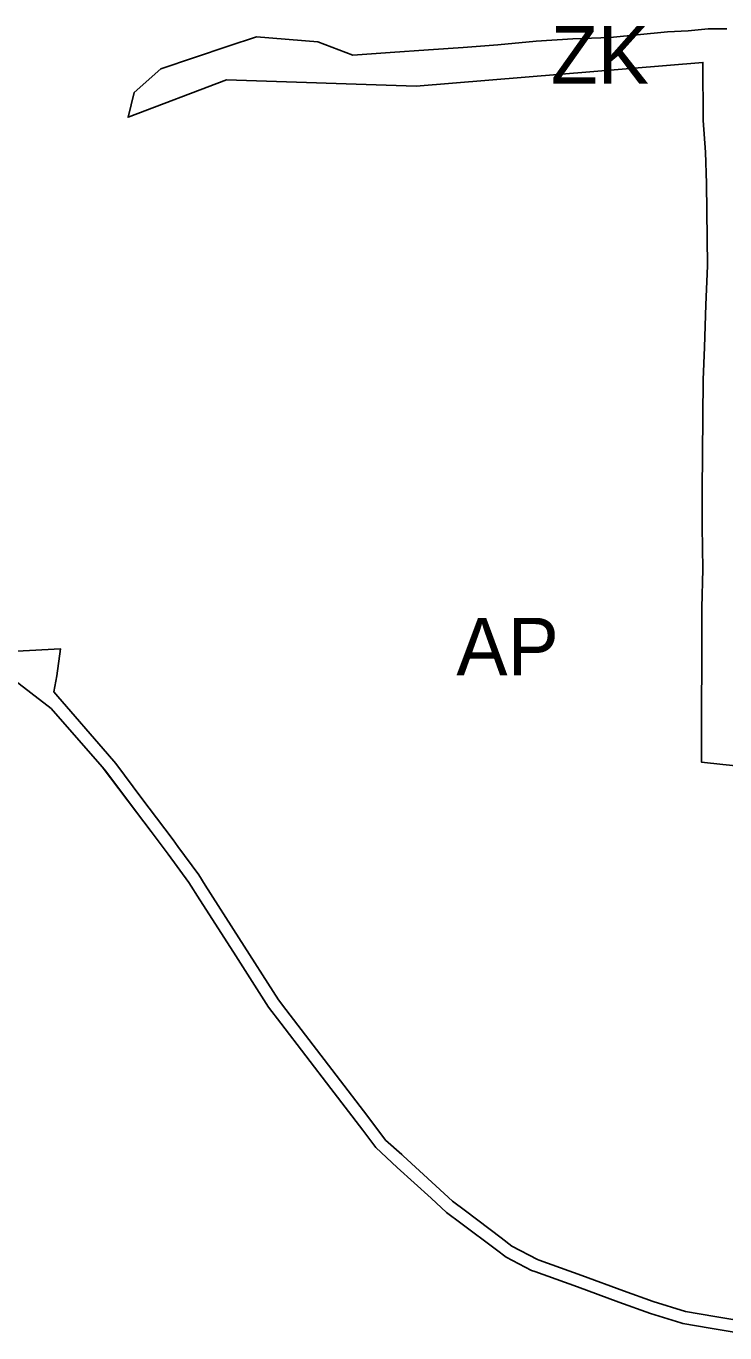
# Model space of a CAD drawing. Extents: x -555509 to -553005, y -1186756 to -1182560.
# Drawn here: x -553469.7 to -553299.5, y -1185459.8 to -1185141.6 of the extents above; entities that cross this region are included whole.
import ezdxf

# ---------------------------------------------------------------- set-up
doc = ezdxf.new("R2010")
doc.units = 0
for name, color, linetype in [('Level 26', 7, 'Continuous'), ('Level 59', 7, 'Continuous'), ('OBRYS_PLOCH', 7, 'Continuous'), ('stav_AP', 7, 'Continuous'), ('stav_ZK', 7, 'Continuous')]:
    doc.layers.add(name, color=color, linetype=linetype)

msp = doc.modelspace()

# ---------------------------------------------------------------- linework, layer by layer
at = {"layer": 'Level 26'}
for p, q in [((-553461.36, -1185293.2), (-553476.51, -1185294.08)), ((-553462.26, -1185299.83), (-553461.36, -1185293.2)), ((-553462.95, -1185303.71), (-553462.26, -1185299.83)), ((-553462, -1185304.81), (-553462.95, -1185303.71)), ((-553449.94, -1185318.8), (-553462, -1185304.81)), ((-553447.88, -1185321.19), (-553449.94, -1185318.8)), ((-553441.55, -1185329.66), (-553447.88, -1185321.19)), ((-553451.19, -1185321.97), (-553450.28, -1185323)), ((-553450.28, -1185323), (-553442.81, -1185332.99)), ((-553438.01, -1185334.39), (-553441.55, -1185329.66)), ((-553433.89, -1185339.72), (-553438.01, -1185334.39)), ((-553432.77, -1185341.4), (-553433.89, -1185339.72)), ((-553427.7, -1185348.29), (-553432.77, -1185341.4)), ((-553426.09, -1185350.82), (-553427.7, -1185348.29)), ((-553417.9, -1185363.63), (-553426.09, -1185350.82)), ((-553408.27, -1185378.71), (-553417.9, -1185363.63)), ((-553406.48, -1185381.05), (-553408.27, -1185378.71)), ((-553410.67, -1185380.52), (-553407.73, -1185384.36)), ((-553394.24, -1185397.05), (-553406.48, -1185381.05)), ((-553386.51, -1185407.16), (-553394.24, -1185397.05)), ((-553382.16, -1185412.85), (-553386.51, -1185407.16)), ((-553378.22, -1185416.39), (-553382.16, -1185412.85)), ((-553384.55, -1185414.66), (-553379.38, -1185419.52)), ((-553377.9, -1185416.68), (-553378.22, -1185416.39)), ((-553369.95, -1185423.98), (-553377.9, -1185416.68)), ((-553379.38, -1185419.52), (-553371.11, -1185427.02)), ((-553365.88, -1185427.72), (-553369.95, -1185423.98)), ((-553371.11, -1185427.02), (-553367.32, -1185430.47)), ((-553362.73, -1185430.11), (-553365.88, -1185427.72)), ((-553367.32, -1185430.47), (-553363.86, -1185433.06)), ((-553354.06, -1185436.68), (-553362.73, -1185430.11)), ((-553351.41, -1185438.69), (-553354.06, -1185436.68)), ((-553345.21, -1185441.93), (-553351.41, -1185438.69)), ((-553352.8, -1185441.34), (-553346.6, -1185444.59)), ((-553344.81, -1185442.08), (-553345.21, -1185441.93)), ((-553334.41, -1185445.85), (-553344.81, -1185442.08)), ((-553346.6, -1185444.59), (-553345.86, -1185444.86)), ((-553345.86, -1185444.86), (-553335.47, -1185448.63)), ((-553335.47, -1185448.63), (-553325.34, -1185452.31)), ((-553324.21, -1185449.55), (-553334.41, -1185445.85)), ((-553317.03, -1185452.16), (-553324.21, -1185449.55)), ((-553325.34, -1185452.31), (-553317.68, -1185455.08)), ((-553317.68, -1185455.08), (-553310.28, -1185457.34)), ((-553309.09, -1185454.58), (-553317.03, -1185452.16)), ((-553301.98, -1185455.8), (-553309.09, -1185454.58)), ((-553310.28, -1185457.34), (-553309.74, -1185457.51)), ((-553309.74, -1185457.51), (-553303.08, -1185458.65)), ((-553295.66, -1185456.88), (-553301.98, -1185455.8)), ((-553303.08, -1185458.65), (-553296.31, -1185459.81))]:
    msp.add_line(p, q, dxfattribs=at)
for points in [[(-553491.57, -1185286.72), (-553477.5, -1185297.16), (-553463.63, -1185307.78), (-553451.19, -1185321.97)], [(-553442.81, -1185332.99), (-553439.25, -1185337.74), (-553435.17, -1185343.2), (-553430.1, -1185350.1), (-553427.4, -1185354.33), (-553419.21, -1185367.14), (-553410.67, -1185380.52)], [(-553407.73, -1185384.36), (-553395.51, -1185400.33), (-553387.75, -1185410.47), (-553384.55, -1185414.66)], [(-553363.86, -1185433.06), (-553355.14, -1185439.59), (-553352.8, -1185441.34)]]:
    msp.add_lwpolyline(points, dxfattribs=at)
at = {"layer": 'OBRYS_PLOCH'}
for p, q in [((-553299.05, -1185142.26), (-553303.58, -1185142.29)), ((-553304.88, -1185150.44), (-553304.86, -1185164.54)), ((-553304.86, -1185164.54), (-553304.27, -1185172.27)), ((-553304.27, -1185172.27), (-553303.98, -1185179.92)), ((-553303.98, -1185179.92), (-553303.77, -1185199.96)), ((-553303.77, -1185199.96), (-553304.15, -1185209.46)), ((-553304.15, -1185209.46), (-553304.47, -1185219.75)), ((-553304.47, -1185219.75), (-553304.86, -1185227.72)), ((-553304.86, -1185227.72), (-553305.06, -1185254.75)), ((-553305.06, -1185254.75), (-553305.04, -1185263.47)), ((-553305.04, -1185263.47), (-553304.94, -1185273.82)), ((-553304.94, -1185273.82), (-553305.15, -1185283.22)), ((-553305.15, -1185283.22), (-553305.23, -1185320.87)), ((-553461.36, -1185293.2), (-553476.51, -1185294.08)), ((-553462.26, -1185299.83), (-553461.36, -1185293.2)), ((-553462.95, -1185303.71), (-553462.26, -1185299.83)), ((-553462, -1185304.81), (-553462.95, -1185303.71)), ((-553449.94, -1185318.8), (-553462, -1185304.81)), ((-553447.88, -1185321.19), (-553449.94, -1185318.8)), ((-553441.55, -1185329.66), (-553447.88, -1185321.19)), ((-553305.23, -1185320.87), (-553300.03, -1185321.4)), ((-553300.03, -1185321.4), (-553296.05, -1185321.81)), ((-553451.19, -1185321.97), (-553450.28, -1185323)), ((-553450.28, -1185323), (-553442.81, -1185332.99)), ((-553438.01, -1185334.39), (-553441.55, -1185329.66)), ((-553433.89, -1185339.72), (-553438.01, -1185334.39)), ((-553432.77, -1185341.4), (-553433.89, -1185339.72)), ((-553427.7, -1185348.29), (-553432.77, -1185341.4)), ((-553426.09, -1185350.82), (-553427.7, -1185348.29)), ((-553417.9, -1185363.63), (-553426.09, -1185350.82)), ((-553408.27, -1185378.71), (-553417.9, -1185363.63)), ((-553406.48, -1185381.05), (-553408.27, -1185378.71)), ((-553410.67, -1185380.52), (-553407.73, -1185384.36)), ((-553394.24, -1185397.05), (-553406.48, -1185381.05)), ((-553386.51, -1185407.16), (-553394.24, -1185397.05)), ((-553382.16, -1185412.85), (-553386.51, -1185407.16)), ((-553378.22, -1185416.39), (-553382.16, -1185412.85)), ((-553384.55, -1185414.66), (-553379.38, -1185419.52)), ((-553377.9, -1185416.68), (-553378.22, -1185416.39)), ((-553369.95, -1185423.98), (-553377.9, -1185416.68)), ((-553379.38, -1185419.52), (-553371.11, -1185427.02)), ((-553365.88, -1185427.72), (-553369.95, -1185423.98)), ((-553371.11, -1185427.02), (-553367.32, -1185430.47)), ((-553362.73, -1185430.11), (-553365.88, -1185427.72)), ((-553367.32, -1185430.47), (-553363.86, -1185433.06)), ((-553354.06, -1185436.68), (-553362.73, -1185430.11)), ((-553351.41, -1185438.69), (-553354.06, -1185436.68)), ((-553345.21, -1185441.93), (-553351.41, -1185438.69)), ((-553352.8, -1185441.34), (-553346.6, -1185444.59)), ((-553344.81, -1185442.08), (-553345.21, -1185441.93)), ((-553334.41, -1185445.85), (-553344.81, -1185442.08)), ((-553346.6, -1185444.59), (-553345.86, -1185444.86)), ((-553345.86, -1185444.86), (-553335.47, -1185448.63)), ((-553335.47, -1185448.63), (-553325.34, -1185452.31)), ((-553325.34, -1185452.31), (-553335.47, -1185448.63)), ((-553324.21, -1185449.55), (-553334.41, -1185445.85)), ((-553317.03, -1185452.16), (-553324.21, -1185449.55)), ((-553325.34, -1185452.31), (-553317.68, -1185455.08)), ((-553317.68, -1185455.08), (-553325.34, -1185452.31)), ((-553317.68, -1185455.08), (-553310.28, -1185457.34)), ((-553310.28, -1185457.34), (-553317.68, -1185455.08)), ((-553309.09, -1185454.58), (-553317.03, -1185452.16)), ((-553301.98, -1185455.8), (-553309.09, -1185454.58)), ((-553310.28, -1185457.34), (-553309.74, -1185457.51)), ((-553309.74, -1185457.51), (-553310.28, -1185457.34)), ((-553309.74, -1185457.51), (-553303.08, -1185458.65)), ((-553303.08, -1185458.65), (-553309.74, -1185457.51)), ((-553295.66, -1185456.88), (-553301.98, -1185455.8)), ((-553303.08, -1185458.65), (-553296.31, -1185459.81)), ((-553296.31, -1185459.81), (-553303.08, -1185458.65))]:
    msp.add_line(p, q, dxfattribs=at)
for points in [[(-553296.05, -1185321.81), (-553300.03, -1185321.4), (-553305.23, -1185320.87), (-553305.15, -1185283.22), (-553304.94, -1185273.82), (-553305.04, -1185263.47), (-553305.06, -1185254.75), (-553304.86, -1185227.72), (-553304.47, -1185219.75), (-553304.15, -1185209.46), (-553303.77, -1185199.96), (-553303.98, -1185179.92), (-553304.27, -1185172.27), (-553304.86, -1185164.54), (-553304.88, -1185150.44), (-553374.7, -1185156.24), (-553420.95, -1185154.69), (-553444.89, -1185163.79), (-553443.4, -1185157.77), (-553436.91, -1185151.99), (-553420.48, -1185146.5), (-553413.61, -1185144.17), (-553398.69, -1185145.4), (-553390.14, -1185148.64), (-553381.08, -1185148.03), (-553371.73, -1185147.36), (-553363.3, -1185146.77), (-553354.87, -1185146.18), (-553345.54, -1185145.26), (-553336.55, -1185144.71), (-553327.47, -1185144.33), (-553313.48, -1185143), (-553308.48, -1185142.76), (-553303.58, -1185142.29), (-553299.05, -1185142.26)], [(-553303.58, -1185142.29), (-553308.48, -1185142.76), (-553313.48, -1185143), (-553327.47, -1185144.33), (-553336.55, -1185144.71), (-553345.54, -1185145.26), (-553354.87, -1185146.18), (-553363.3, -1185146.77), (-553371.73, -1185147.36), (-553381.08, -1185148.03), (-553390.14, -1185148.64), (-553398.69, -1185145.4), (-553413.61, -1185144.17), (-553420.48, -1185146.5), (-553436.91, -1185151.99), (-553443.4, -1185157.77), (-553444.89, -1185163.79), (-553420.95, -1185154.69)], [(-553420.95, -1185154.69), (-553374.7, -1185156.24), (-553304.88, -1185150.44)], [(-553491.57, -1185286.72), (-553477.5, -1185297.16), (-553463.63, -1185307.78), (-553451.19, -1185321.97)], [(-553476.51, -1185294.08), (-553461.36, -1185293.2), (-553462.26, -1185299.83)], [(-553335.47, -1185448.63), (-553345.86, -1185444.86), (-553346.6, -1185444.59), (-553352.8, -1185441.34), (-553355.14, -1185439.59), (-553363.86, -1185433.06), (-553367.32, -1185430.47), (-553371.11, -1185427.02), (-553379.38, -1185419.52), (-553384.55, -1185414.66), (-553387.75, -1185410.47), (-553395.51, -1185400.33), (-553407.73, -1185384.36), (-553410.67, -1185380.52), (-553419.21, -1185367.14), (-553427.4, -1185354.33), (-553430.1, -1185350.1), (-553435.17, -1185343.2), (-553439.25, -1185337.74), (-553442.81, -1185332.99), (-553451.19, -1185321.97), (-553463.63, -1185307.78), (-553477.5, -1185297.16)], [(-553462.26, -1185299.83), (-553462.95, -1185303.71), (-553462, -1185304.81), (-553449.94, -1185318.8), (-553447.88, -1185321.19), (-553441.55, -1185329.66), (-553438.01, -1185334.39), (-553433.89, -1185339.72), (-553432.77, -1185341.4), (-553427.7, -1185348.29), (-553426.09, -1185350.82), (-553417.9, -1185363.63), (-553408.27, -1185378.71), (-553406.48, -1185381.05), (-553394.24, -1185397.05), (-553386.51, -1185407.16), (-553382.16, -1185412.85), (-553378.22, -1185416.39), (-553377.9, -1185416.68), (-553369.95, -1185423.98), (-553365.88, -1185427.72), (-553362.73, -1185430.11), (-553354.06, -1185436.68), (-553351.41, -1185438.69), (-553345.21, -1185441.93), (-553344.81, -1185442.08), (-553334.41, -1185445.85), (-553324.21, -1185449.55), (-553317.03, -1185452.16), (-553309.09, -1185454.58), (-553301.98, -1185455.8), (-553295.66, -1185456.88)], [(-553442.81, -1185332.99), (-553439.25, -1185337.74), (-553435.17, -1185343.2), (-553430.1, -1185350.1), (-553427.4, -1185354.33), (-553419.21, -1185367.14), (-553410.67, -1185380.52)], [(-553407.73, -1185384.36), (-553395.51, -1185400.33), (-553387.75, -1185410.47), (-553384.55, -1185414.66)], [(-553363.86, -1185433.06), (-553355.14, -1185439.59), (-553352.8, -1185441.34)]]:
    msp.add_lwpolyline(points, dxfattribs=at)
at = {"layer": 'stav_AP'}
for p, q in [((-553325.34, -1185452.31), (-553335.47, -1185448.63)), ((-553317.68, -1185455.08), (-553325.34, -1185452.31)), ((-553310.28, -1185457.34), (-553317.68, -1185455.08)), ((-553309.74, -1185457.51), (-553310.28, -1185457.34)), ((-553303.08, -1185458.65), (-553309.74, -1185457.51)), ((-553296.31, -1185459.81), (-553303.08, -1185458.65))]:
    msp.add_line(p, q, dxfattribs=at)
for points in [[(-553296.05, -1185321.81), (-553300.03, -1185321.4), (-553305.23, -1185320.87), (-553305.15, -1185283.22), (-553304.94, -1185273.82), (-553305.04, -1185263.47), (-553305.06, -1185254.75), (-553304.86, -1185227.72), (-553304.47, -1185219.75), (-553304.15, -1185209.46), (-553303.77, -1185199.96), (-553303.98, -1185179.92), (-553304.27, -1185172.27), (-553304.86, -1185164.54), (-553304.88, -1185150.44), (-553374.7, -1185156.24), (-553420.95, -1185154.69), (-553444.89, -1185163.79), (-553443.4, -1185157.77), (-553436.91, -1185151.99), (-553420.48, -1185146.5), (-553413.61, -1185144.17), (-553398.69, -1185145.4), (-553390.14, -1185148.64), (-553381.08, -1185148.03), (-553371.73, -1185147.36), (-553363.3, -1185146.77), (-553354.87, -1185146.18), (-553345.54, -1185145.26), (-553336.55, -1185144.71), (-553327.47, -1185144.33), (-553313.48, -1185143), (-553308.48, -1185142.76), (-553303.58, -1185142.29), (-553299.05, -1185142.26)], [(-553476.51, -1185294.08), (-553461.36, -1185293.2), (-553462.26, -1185299.83)], [(-553335.47, -1185448.63), (-553345.86, -1185444.86), (-553346.6, -1185444.59), (-553352.8, -1185441.34), (-553355.14, -1185439.59), (-553363.86, -1185433.06), (-553367.32, -1185430.47), (-553371.11, -1185427.02), (-553379.38, -1185419.52), (-553384.55, -1185414.66), (-553387.75, -1185410.47), (-553395.51, -1185400.33), (-553407.73, -1185384.36), (-553410.67, -1185380.52), (-553419.21, -1185367.14), (-553427.4, -1185354.33), (-553430.1, -1185350.1), (-553435.17, -1185343.2), (-553439.25, -1185337.74), (-553442.81, -1185332.99), (-553451.19, -1185321.97), (-553463.63, -1185307.78), (-553477.5, -1185297.16)], [(-553462.26, -1185299.83), (-553462.95, -1185303.71), (-553462, -1185304.81), (-553449.94, -1185318.8), (-553447.88, -1185321.19), (-553441.55, -1185329.66), (-553438.01, -1185334.39), (-553433.89, -1185339.72), (-553432.77, -1185341.4), (-553427.7, -1185348.29), (-553426.09, -1185350.82), (-553417.9, -1185363.63), (-553408.27, -1185378.71), (-553406.48, -1185381.05), (-553394.24, -1185397.05), (-553386.51, -1185407.16), (-553382.16, -1185412.85), (-553378.22, -1185416.39), (-553377.9, -1185416.68), (-553369.95, -1185423.98), (-553365.88, -1185427.72), (-553362.73, -1185430.11), (-553354.06, -1185436.68), (-553351.41, -1185438.69), (-553345.21, -1185441.93), (-553344.81, -1185442.08), (-553334.41, -1185445.85), (-553324.21, -1185449.55), (-553317.03, -1185452.16), (-553309.09, -1185454.58), (-553301.98, -1185455.8), (-553295.66, -1185456.88)]]:
    msp.add_lwpolyline(points, dxfattribs=at)
at = {"layer": 'stav_ZK'}
for p, q in [((-553299.05, -1185142.26), (-553303.58, -1185142.29)), ((-553304.88, -1185150.44), (-553304.86, -1185164.54)), ((-553304.86, -1185164.54), (-553304.27, -1185172.27)), ((-553304.27, -1185172.27), (-553303.98, -1185179.92)), ((-553303.98, -1185179.92), (-553303.77, -1185199.96)), ((-553303.77, -1185199.96), (-553304.15, -1185209.46)), ((-553304.15, -1185209.46), (-553304.47, -1185219.75)), ((-553304.47, -1185219.75), (-553304.86, -1185227.72)), ((-553304.86, -1185227.72), (-553305.06, -1185254.75)), ((-553305.06, -1185254.75), (-553305.04, -1185263.47)), ((-553305.04, -1185263.47), (-553304.94, -1185273.82)), ((-553304.94, -1185273.82), (-553305.15, -1185283.22)), ((-553305.15, -1185283.22), (-553305.23, -1185320.87)), ((-553305.23, -1185320.87), (-553300.03, -1185321.4)), ((-553300.03, -1185321.4), (-553296.05, -1185321.81))]:
    msp.add_line(p, q, dxfattribs=at)
for points in [[(-553303.58, -1185142.29), (-553308.48, -1185142.76), (-553313.48, -1185143), (-553327.47, -1185144.33), (-553336.55, -1185144.71), (-553345.54, -1185145.26), (-553354.87, -1185146.18), (-553363.3, -1185146.77), (-553371.73, -1185147.36), (-553381.08, -1185148.03), (-553390.14, -1185148.64), (-553398.69, -1185145.4), (-553413.61, -1185144.17), (-553420.48, -1185146.5), (-553436.91, -1185151.99), (-553443.4, -1185157.77), (-553444.89, -1185163.79), (-553420.95, -1185154.69)], [(-553420.95, -1185154.69), (-553374.7, -1185156.24), (-553304.88, -1185150.44)]]:
    msp.add_lwpolyline(points, dxfattribs=at)

# ---------------------------------------------------------------- texts
at = {"layer": 'Level 59'}
for s, p in [('ZK', (-553341.95, -1185155.6)), ('AP', (-553364.95, -1185299.7))]:
    msp.add_text(s, height=14, dxfattribs=at).set_placement(p)

doc.saveas('drawing.dxf')
